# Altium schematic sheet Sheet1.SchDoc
size A4; SheetNumber: 1; SheetTotal: 1
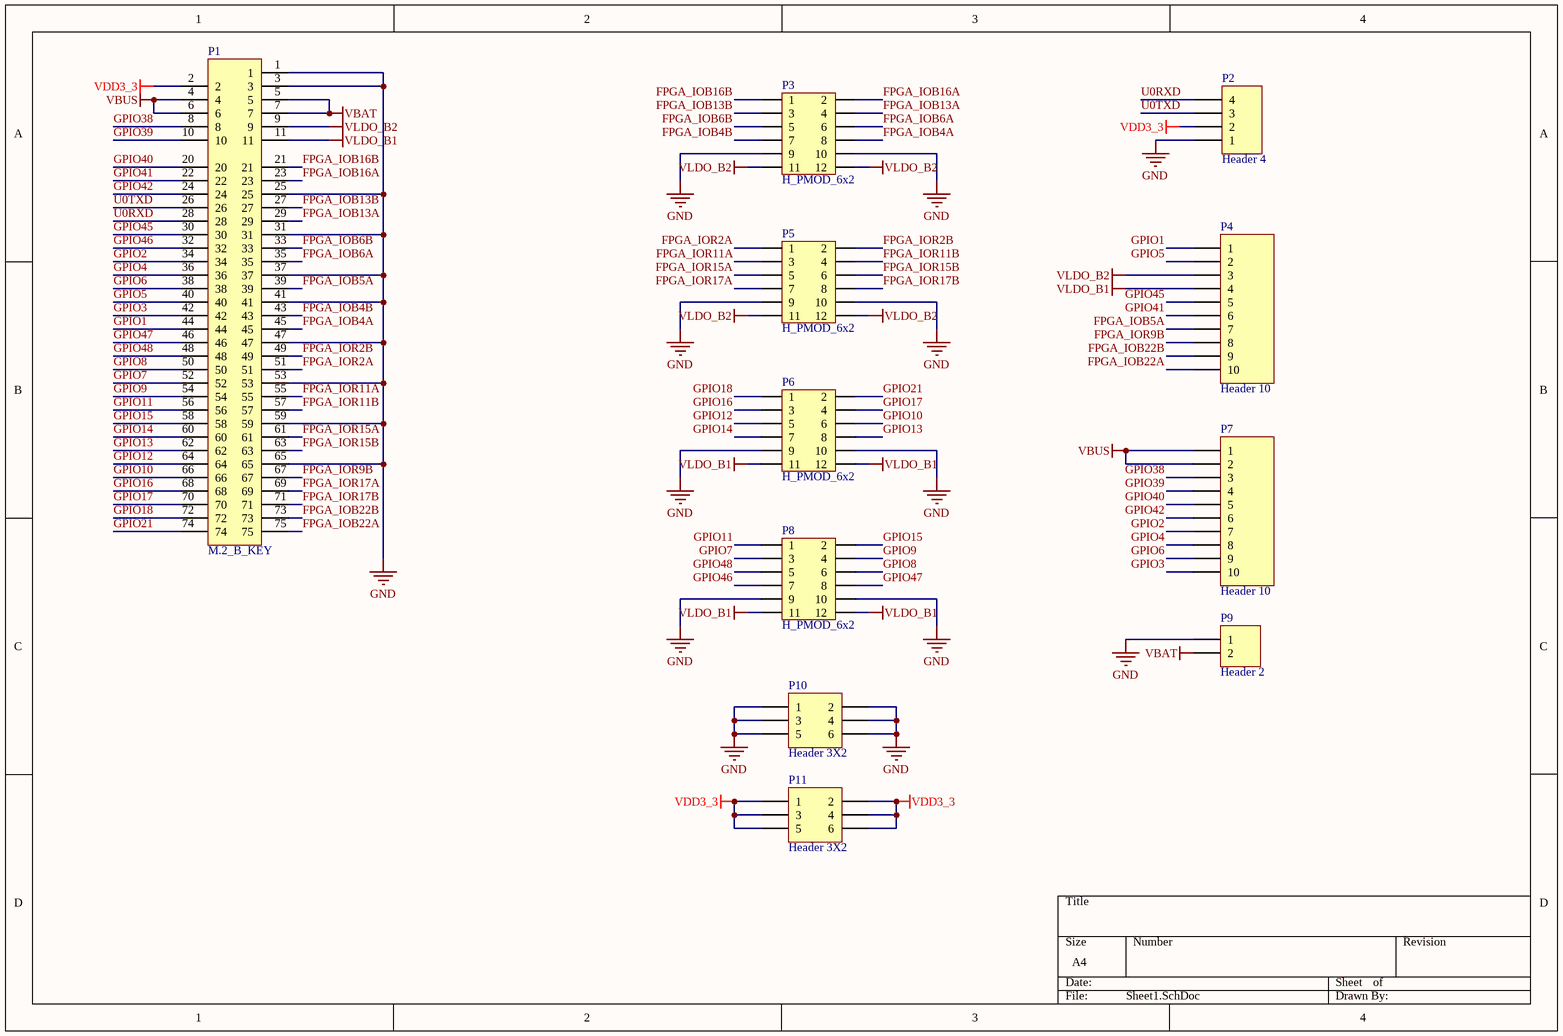
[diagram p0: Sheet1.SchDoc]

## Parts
P1  M.2_B_KEY  [M.2 B KEY M]
P2  Header 4  [H-Header_4P-1.0mm]
P3  H_PMOD_6x2  [PMOD 6x2]
P4  Header 10  [10P_HDR]
P5  H_PMOD_6x2  [PMOD 6x2]
P6  H_PMOD_6x2  [PMOD 6x2]
P7  Header 10  [10P_HDR]
P8  H_PMOD_6x2  [PMOD 6x2]
P9  Header 2  [BAT电池盒]
P10  Header 3X2  [HDR_3x2]
P11  Header 3X2  [HDR_3x2]

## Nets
GND: P1.1 P1.3 P1.25 P1.31 P1.37 P1.41 P1.47 P1.53 P1.59 P1.65 P2.1 P3.9 P3.10 P5.9 P5.10 P6.9 P6.10 P8.9 P8.10 P9.1 P10.1 P10.2 P10.3 P10.4 P10.5 P10.6
VBAT: P1.5 P1.7 P9.2
VBUS: P1.4 P1.6 P7.1 P7.2
VDD3_3: P1.2 P2.2 P11.1 P11.2 P11.3 P11.4 P11.5 P11.6
VLDO_B1: P1.11 P4.4 P6.11 P6.12 P8.11 P8.12
VLDO_B2: P1.9 P3.11 P3.12 P4.3 P5.11 P5.12
FPGA_IOB4A: P1.45 P3.8
FPGA_IOB4B: P1.43 P3.7
FPGA_IOB5A: P1.39 P4.7
FPGA_IOB6A: P1.35 P3.6
FPGA_IOB6B: P1.33 P3.5
FPGA_IOB13A: P1.29 P3.4
FPGA_IOB13B: P1.27 P3.3
FPGA_IOB16A: P1.23 P3.2
FPGA_IOB16B: P1.21 P3.1
FPGA_IOB22A: P1.75 P4.10
FPGA_IOB22B: P1.73 P4.9
FPGA_IOR2A: P1.51 P5.1
FPGA_IOR2B: P1.49 P5.2
FPGA_IOR9B: P1.67 P4.8
FPGA_IOR11A: P1.55 P5.3
FPGA_IOR11B: P1.57 P5.4
FPGA_IOR15A: P1.61 P5.5
FPGA_IOR15B: P1.63 P5.6
FPGA_IOR17A: P1.69 P5.7
FPGA_IOR17B: P1.71 P5.8
GPIO1: P1.44 P4.1
GPIO2: P1.34 P7.7
GPIO3: P1.42 P7.10
GPIO4: P1.36 P7.8
GPIO5: P1.40 P4.2
GPIO6: P1.38 P7.9
GPIO7: P1.52 P8.3
GPIO8: P1.50 P8.6
GPIO9: P1.54 P8.4
GPIO10: P1.66 P6.6
GPIO11: P1.56 P8.1
GPIO12: P1.64 P6.5
GPIO13: P1.62 P6.8
GPIO14: P1.60 P6.7
GPIO15: P1.58 P8.2
GPIO16: P1.68 P6.3
GPIO17: P1.70 P6.4
GPIO18: P1.72 P6.1
GPIO21: P1.74 P6.2
GPIO38: P1.8 P7.3
GPIO39: P1.10 P7.4
GPIO40: P1.20 P7.5
GPIO41: P1.22 P4.6
GPIO42: P1.24 P7.6
GPIO45: P1.30 P4.5
GPIO46: P1.32 P8.7
GPIO47: P1.46 P8.8
GPIO48: P1.48 P8.5
U0RXD: P1.28 P2.4
U0TXD: P1.26 P2.3

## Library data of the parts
P2 = H_Header_4
P4 P7 = H_Header_10
P9 = H_Header_2
P10 P11 = H_Header_3X2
